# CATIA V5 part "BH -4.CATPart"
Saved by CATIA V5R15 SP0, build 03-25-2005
Part number: Part21
Material "Grey Blue": density 7860 kg/m3, Young's modulus 2e+11 Pa, Poisson ratio 0.266
Bounding box of the stored display mesh (mm): x -79 to 79, y -158 to 158, z 0 to 113.2
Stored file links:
  E:\#01 CATIA Lecture Materials\#06 DMU\#11 DMU Page01 KIN EX11\BH -4.CATPart
  C:\Program Files\Dassault Systemes\B20\win_b64\startup\materials\Catalog.CATMaterial
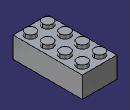
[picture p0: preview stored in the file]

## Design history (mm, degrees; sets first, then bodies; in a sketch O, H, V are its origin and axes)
Body1 (main body), material "Grey Blue"
  Sketch1 on xy-plane, origin (0, 0, 0), H (1, 0, 0), V (0, 1, 0)
    line L1 (-79, 158) -> (79, 158)
    line L2 (79, 158) -> (79, -158)
    line L3 (79, -158) -> (-79, -158)
    line L4 (-79, -158) -> (-79, 158)
    length L2 = 316
    distance L4 L2 = 158
    horizontal: L1 H, L3 H
    vertical: L2 V, L4 V
    symmetry: L2 L4 V, L3 L1 H
  Pad1: profile Sketch1, direction (0, 0, 1), length 96
  Sketch2 on end face of Pad1, origin (0, 0, 96), H (1, 0, 0), V (0, 1, 0)
    circle A1 centre (39.5, -118.5) radius 23.5
    point P1 (39.5, -118.5)
    reference projected line E1 (-79, -158) -> (79, -158) from edge [face of Pad1 from Sketch1.L3 | end face of Pad1]
    reference projected line E2 (79, -158) -> (79, 158) from edge [face of Pad1 from Sketch1.L2 | end face of Pad1]
    radius A1 = 23.5
    distance P1 E1 = 39.5
    distance P1 E2 = 39.5
  Pad2: profile Sketch2, direction (0, 0, 1), length 17.2
  RectPattern1: of Pad2, direction 1 instances 2, spacing 79, along xy-plane reversed, direction 2 instances 4, spacing 79, along xy-plane
  Shell1: ExtOffset 0, Face start face of Pad1, IntOffset 15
